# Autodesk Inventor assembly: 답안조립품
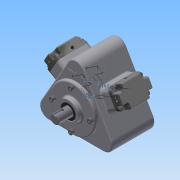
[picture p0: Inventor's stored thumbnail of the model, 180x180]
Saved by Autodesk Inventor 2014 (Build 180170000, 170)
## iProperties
Created: 2015-06
Part Number: 답안조립품
Document SubType Name: Assembly
Designer: Administrator
Mass: 5318.58 g
Surface Area: 2414.93 cm^2
Volume: 1564.62 cm^3
Density: 3.39928 g/cm^3
Author: Administrator
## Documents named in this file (20)
- C:\Users\Administrator\Desktop\350605V1048\답안조립품.iam
- C:\Users\Administrator\Desktop\350605V1048\본체.ipt
- C:\Users\Administrator\Desktop\350605V1048\앞커버.ipt
- C:\Users\Administrator\Desktop\350605V1048\M6x0.7x20.ipt
- M6x0.7x20.ipt
- C:\Users\Administrator\Desktop\350605V1048\오일실.ipt
- 오일실.ipt
- C:\Users\Administrator\Desktop\350605V1048\베어링 NA 4904.ipt
- 베어링 NA 4904.ipt
- C:\Users\Administrator\Desktop\350605V1048\편심축.ipt
- C:\Users\Administrator\Desktop\350605V1048\헤더커버.ipt
- 헤더커버.ipt
- C:\Users\Administrator\Desktop\350605V1048\부시.ipt
- C:\Users\Administrator\Desktop\350605V1048\슬라이드.ipt
- C:\Users\Administrator\Desktop\350605V1048\8-스프링.ipt
- C:\Users\Administrator\Desktop\350605V1048\9-스프링.ipt
- C:\Users\Administrator\Desktop\350605V1048\10-스프링.ipt
- C:\Users\Administrator\Desktop\350605V1048\11-스프링.ipt
- C:\Users\Administrator\Desktop\350605V1048\M4x0.5x16.ipt
- M4x0.5x16.ipt
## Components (18 placed, 7 different names)
1. M6x0.7x20:1
2. M6x0.7x20:2
3. M6x0.7x20:3
4. M6x0.7x20:4
5. 헤더커버:1
6. 헤더커버:2
7. 8-스프링:1
8. 9-스프링:1
9. 10-스프링:1
10. 11-스프링:1
11. M4x0.5x16:1
12. M4x0.5x16:2
13. M4x0.5x16:3
14. M4x0.5x16:4
15. M4x0.5x16:5
16. M4x0.5x16:6
17. M4x0.5x16:7
18. M4x0.5x16:8
